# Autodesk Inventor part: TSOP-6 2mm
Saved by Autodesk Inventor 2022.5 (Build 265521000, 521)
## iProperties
Created: 2024-12
Part Number: TSOP-6 2mm
Material: Generic
Document SubType Name: Modeling
Designer: AdminForWorker
Density: 1 g/cm^3
Appearance: Default
Title: TSOP-6 2mm v1
Author: AdminForWorker
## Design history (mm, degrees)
feature "Body1" [lead]
feature "lead2"
feature "lead1"
feature "lead3"
feature "opt_lead" [lead]
feature "lead5"
feature "lead4"
body "Solid1"
body "Solid2"
body "Solid3"
body "Solid4"
body "Solid5"
body "Solid6"
body "Solid7"
